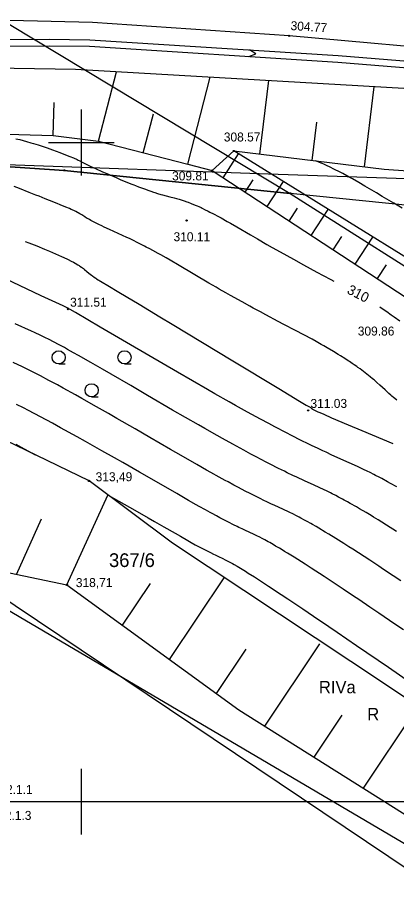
# Model space of a CAD drawing. Extents: x 7477803 to 7478145, y 5500698 to 5500984.
# Drawn here: x 7477945.2 to 7477973.9, y 5500742.3 to 5500809.5 of the extents above; entities that cross this region are included whole.
import ezdxf

# ---------------------------------------------------------------- set-up
doc = ezdxf.new("R2010")
doc.units = 0
for name, color, linetype in [('203-Punkt załamania granicy działki nie stabilizowany', 7, 'Continuous'), ('gr_dzialki', 7, 'Continuous'), ('gr_klasy', 7, 'Continuous'), ('jezdnia', 7, 'Continuous'), ('nr_dzialki', 7, 'Continuous'), ('ogr_symb', 7, 'Continuous'), ('opis_klasy', 7, 'Continuous'), ('opis_uzytek', 7, 'Continuous'), ('pkt_wys', 7, 'Continuous'), ('robocza49', 7, 'Continuous'), ('robocza50', 7, 'Continuous'), ('rowy', 7, 'Continuous'), ('skarp_wypel', 7, 'Continuous'), ('skarpa_dol', 7, 'Continuous'), ('skarpa_gora', 7, 'Continuous'), ('warst_ciagla', 7, 'Continuous'), ('warst_opis', 7, 'Continuous'), ('warst_pogrub', 7, 'Continuous'), ('warst_przeryw', 7, 'Continuous'), ('zakresy', 7, 'Continuous'), ('zielen', 7, 'Continuous')]:
    doc.layers.add(name, color=color, linetype=linetype)

# ---------------------------------------------------------------- blocks, each defined once
blk = doc.blocks.new('203')
blk.add_circle((0, 0), 0.045)
blk = doc.blocks.new('801')
at = {"layer": 'pkt_wys'}
blk.add_circle((0, 0), 0.045, dxfattribs=at)
blk.add_circle((0, 0), 0.045, dxfattribs=at)
blk = doc.blocks.new('941_5')
at = {"layer": 'zielen'}
for p, q in [((-2.5, 0.46), (-2, 0.46)), ((2.5, 0.46), (3, 0.46)), ((0, -2.04), (0.5, -2.04))]:
    blk.add_line(p, q, dxfattribs=at)
for centre in [(-2.503, 0.963), (2.497, 0.963), (-0.003, -1.537)]:
    blk.add_circle(centre, 0.5, dxfattribs=at)
blk = doc.blocks.new('801_5_1')
at = {"layer": 'pkt_wys'}
blk.add_circle((0, 0), 0.05, dxfattribs=at)
blk.add_circle((0, 0), 0.05, dxfattribs=at)
blk = doc.blocks.new('801_5_3')
at = {"layer": 'pkt_wys'}
blk.add_circle((0, 0), 0.05, dxfattribs=at)
blk.add_circle((0, 0), 0.05, dxfattribs=at)

msp = doc.modelspace()

# ---------------------------------------------------------------- linework, layer by layer
at = {"layer": 'gr_dzialki'}
for points in [[(7477942.51, 5500810.15), (7477965.87, 5500796.14)], [(7477933.39, 5500798.91), (7477948.7, 5500797.88)], [(7477948.7, 5500797.88), (7477965.87, 5500796.14)], [(7477965.87, 5500796.14), (7478019.23, 5500762.35)], [(7477980.59, 5500794.64), (7477965.87, 5500796.14)]]:
    msp.add_lwpolyline(points, dxfattribs=at)
at = {"layer": 'gr_klasy'}
for points in [[(7477948.7, 5500797.88), (7477933.39, 5500798.91)], [(7477965.87, 5500796.14), (7477948.7, 5500797.88)], [(7477980.59, 5500794.64), (7477965.87, 5500796.14)]]:
    msp.add_lwpolyline(points, dxfattribs=at)
at = {"layer": 'jezdnia'}
for points in [[(7478007.787, 5500804.444), (7477996.226, 5500805.272), (7477980.454, 5500806.765), (7477965.783, 5500808.078), (7477950.842, 5500809.092), (7477941.412, 5500809.312), (7477933.642, 5500808.883), (7477925.833, 5500807.985), (7477921.044, 5500806.84), (7477908.409, 5500802.106), (7477902.302, 5500799.559), (7477897.005, 5500796.683), (7477891.579, 5500793.077), (7477886.813, 5500789.372), (7477881.349, 5500784.496), (7477881.326, 5500784.471)], [(7477992.069, 5500728.595), (7477992.586, 5500729.366), (7477990.061, 5500731.06), (7477991.702, 5500733.507), (7477933.306, 5500772.671), (7477931.61, 5500770.142), (7477929.08, 5500771.838), (7477927.439, 5500769.391), (7477926.244, 5500770.192), (7477925.336, 5500768.842)]]:
    msp.add_lwpolyline(points, dxfattribs=at)
at = {"layer": 'ogr_symb'}
msp.add_lwpolyline([(7477891.276, 5500779.392), (7477896.666, 5500786.743), (7477921.734, 5500797.99), (7477944.284, 5500798.315), (7477964.224, 5500797.617), (7478003.756, 5500796.28)], dxfattribs=at)
at = {"layer": 'robocza49'}
for p, q in [((7477950, 5500797.5), (7477950, 5500802.5)), ((7477947.5, 5500800), (7477952.5, 5500800)), ((7477950, 5500750), (7477950, 5500752.5)), ((7478000, 5500750), (7477937.375, 5500750)), ((7477950, 5500747.5), (7477950, 5500750))]:
    msp.add_line(p, q, dxfattribs=at)
at = {"layer": 'rowy'}
for points in [[(7477903.253, 5500798.785), (7477908.747, 5500801.483), (7477910.219, 5500802.081), (7477915.822, 5500804.075), (7477918.6, 5500805.006), (7477920.886, 5500805.655), (7477923.298, 5500806.18), (7477925.514, 5500806.496), (7477928.461, 5500806.935), (7477932.972, 5500807.407), (7477936.072, 5500807.618), (7477938.432, 5500807.783), (7477947.546, 5500807.824), (7477950.631, 5500807.793), (7477969.517, 5500806.584), (7477989.191, 5500804.994), (7477997.207, 5500804.282)], [(7477882.663, 5500783.628), (7477883.714, 5500784.691), (7477887.616, 5500787.993), (7477891.069, 5500790.733), (7477893.37, 5500792.367), (7477898.157, 5500795.46), (7477901.645, 5500797.349), (7477903.482, 5500798.34), (7477908.951, 5500801.027), (7477910.397, 5500801.613), (7477915.985, 5500803.602), (7477918.748, 5500804.528), (7477921.007, 5500805.169), (7477923.387, 5500805.687), (7477925.587, 5500806.001), (7477928.524, 5500806.439), (7477933.015, 5500806.909), (7477936.106, 5500807.119), (7477938.45, 5500807.283), (7477947.545, 5500807.324), (7477950.612, 5500807.294), (7477969.481, 5500806.086), (7477989.149, 5500804.495), (7477997.163, 5500803.784)], [(7477962.73, 5500806.518), (7477963.244, 5500806.716), (7477962.762, 5500807.017)]]:
    msp.add_lwpolyline(points, dxfattribs=at)
at = {"layer": 'skarp_wypel'}
for p, q in [((7477951.313, 5500800.09), (7477952.671, 5500805.347)), ((7477958.091, 5500798.34), (7477959.796, 5500804.94)), ((7477963.565, 5500799.118), (7477964.241, 5500804.686)), ((7477971.507, 5500798.154), (7477972.244, 5500804.228)), ((7477947.862, 5500800.525), (7477947.936, 5500803.038)), ((7477954.702, 5500799.215), (7477955.468, 5500802.179)), ((7477967.536, 5500798.636), (7477967.889, 5500801.546)), ((7477960.759, 5500797.321), (7477961.942, 5500799.135)), ((7477962.434, 5500796.228), (7477963.039, 5500797.155)), ((7477964.109, 5500795.135), (7477965.345, 5500797.03)), ((7477965.784, 5500794.042), (7477966.415, 5500795.01)), ((7477967.459, 5500792.95), (7477968.748, 5500794.925)), ((7477969.134, 5500791.857), (7477969.792, 5500792.865)), ((7477970.809, 5500790.764), (7477972.151, 5500792.82)), ((7477972.485, 5500789.671), (7477973.168, 5500790.719)), ((7477948.908, 5500766.44), (7477952.002, 5500773.26)), ((7477945.07, 5500767.244), (7477946.982, 5500771.458)), ((7477953.119, 5500763.388), (7477955.248, 5500766.561)), ((7477956.698, 5500760.795), (7477960.889, 5500767.043)), ((7477963.94, 5500755.734), (7477968.125, 5500761.973)), ((7477960.276, 5500758.201), (7477962.528, 5500761.557)), ((7477967.68, 5500753.381), (7477969.808, 5500756.554)), ((7477971.42, 5500751.028), (7477975.36, 5500756.902))]:
    msp.add_line(p, q, dxfattribs=at)
at = {"layer": 'skarpa_dol'}
msp.add_lwpolyline([(7478003.179, 5500722.859), (7478004.323, 5500725.251), (7478005.298, 5500730.032), (7478003.066, 5500732.439), (7477998.881, 5500736.525), (7477989.029, 5500747.324), (7477982.233, 5500752.776), (7477973.187, 5500758.837), (7477956.935, 5500769.599), (7477950.58, 5500774.332), (7477941.825, 5500778.562), (7477933.581, 5500781.953), (7477926.713, 5500780.256), (7477921.899, 5500775.451), (7477920.234, 5500772.903)], dxfattribs=at)
at = {"layer": 'skarpa_gora'}
for points in [[(7478007.749, 5500802.055), (7477980.618, 5500803.745), (7477949.546, 5500805.521), (7477933.975, 5500805.774), (7477921.168, 5500803.47), (7477908.381, 5500800.266), (7477897.978, 5500794.654), (7477888.325, 5500787.474), (7477883.93, 5500782.828)], [(7477889.282, 5500779.695), (7477895.338, 5500786.582), (7477897.871, 5500788.956), (7477903.767, 5500792.731), (7477909.966, 5500795.925), (7477913.206, 5500797.237), (7477923.556, 5500799.006), (7477930.426, 5500800.345), (7477933.868, 5500800.938), (7477937.366, 5500800.835), (7477947.862, 5500800.525), (7477951.313, 5500800.09), (7477958.091, 5500798.34), (7477959.924, 5500797.862), (7477975.395, 5500787.769), (7477983.174, 5500779.337)], [(7477984.422, 5500781.659), (7477976.623, 5500790.05), (7477961.582, 5500799.354), (7477959.924, 5500797.862)], [(7477961.582, 5500799.354), (7477973.014, 5500797.966), (7477992.005, 5500796.627), (7477997.444, 5500794.449), (7478004.059, 5500795.357)], [(7477924.585, 5500769.172), (7477928.36, 5500773.878), (7477930.919, 5500774.6), (7477933.4, 5500774.083), (7477944.537, 5500767.355), (7477948.908, 5500766.44), (7477961.969, 5500756.974), (7477978.9, 5500746.323), (7477991.003, 5500734.936), (7477993.436, 5500731.709), (7477996, 5500728.251), (7477997.928, 5500724.248)]]:
    msp.add_lwpolyline(points, dxfattribs=at)
at = {"layer": 'warst_ciagla'}
for points in [[(7477974.377, 5500795.015), (7477973.724, 5500795.399), (7477972.855, 5500795.913), (7477972.421, 5500796.172), (7477971.542, 5500796.693), (7477971.081, 5500796.961), (7477970.594, 5500797.236), (7477970.338, 5500797.377), (7477969.86, 5500797.634), (7477969.613, 5500797.763), (7477969.235, 5500797.954), (7477968.853, 5500798.14), (7477968.662, 5500798.231), (7477968.408, 5500798.347), (7477968.282, 5500798.403), (7477968.095, 5500798.484), (7477967.818, 5500798.598)], [(7477945.729, 5500792.496), (7477946.015, 5500792.388), (7477946.21, 5500792.314), (7477946.605, 5500792.158), (7477947.196, 5500791.917), (7477947.576, 5500791.758), (7477947.819, 5500791.654), (7477948.269, 5500791.457), (7477948.495, 5500791.355), (7477948.89, 5500791.17), (7477949.007, 5500791.114), (7477949.219, 5500791.007), (7477949.407, 5500790.908), (7477949.52, 5500790.845), (7477949.721, 5500790.727), (7477949.822, 5500790.663), (7477949.884, 5500790.622), (7477950.001, 5500790.542), (7477950.154, 5500790.429), (7477950.246, 5500790.357), (7477950.41, 5500790.224), (7477950.576, 5500790.09), (7477950.77, 5500789.937), (7477950.856, 5500789.871), (7477950.971, 5500789.786), (7477951.097, 5500789.697), (7477951.149, 5500789.664), (7477951.592, 5500789.409), (7477952.01, 5500789.162), (7477952.857, 5500788.656), (7477953.404, 5500788.328), (7477954.38, 5500787.74), (7477955.971, 5500786.781), (7477956.891, 5500786.226), (7477961.495, 5500783.441), (7477964.992, 5500781.33), (7477965.788, 5500780.851), (7477966.562, 5500780.388), (7477966.826, 5500780.231), (7477967.077, 5500780.083), (7477967.268, 5500779.976), (7477967.317, 5500779.948), (7477967.378, 5500779.911), (7477967.405, 5500779.893), (7477967.444, 5500779.867), (7477967.49, 5500779.833), (7477967.51, 5500779.816), (7477967.54, 5500779.792), (7477967.562, 5500779.777), (7477967.613, 5500779.747), (7477967.755, 5500779.676), (7477967.972, 5500779.575), (7477968.123, 5500779.508), (7477968.409, 5500779.382), (7477968.998, 5500779.126), (7477970.264, 5500778.587), (7477971.305, 5500778.148), (7477973.668, 5500777.157)], [(7477973.951, 5500770.497), (7477973.191, 5500770.978), (7477972.822, 5500771.207), (7477972.551, 5500771.374), (7477972.196, 5500771.59), (7477972.022, 5500771.695), (7477971.637, 5500771.925), (7477971.14, 5500772.217), (7477970.898, 5500772.356), (7477970.427, 5500772.623), (7477970.223, 5500772.735), (7477969.958, 5500772.881), (7477969.827, 5500772.951), (7477969.539, 5500773.105), (7477969.328, 5500773.215), (7477969.054, 5500773.355), (7477968.92, 5500773.422), (7477968.625, 5500773.566), (7477968.433, 5500773.659), (7477968.057, 5500773.835), (7477967.687, 5500774.004), (7477966.943, 5500774.34), (7477966.363, 5500774.606), (7477966.059, 5500774.749), (7477965.638, 5500774.951), (7477965.422, 5500775.057), (7477964.975, 5500775.279), (7477964.352, 5500775.594), (7477964.029, 5500775.76), (7477963.273, 5500776.156), (7477962.88, 5500776.365), (7477962.341, 5500776.654), (7477962.065, 5500776.804), (7477961.5, 5500777.113), (7477960.718, 5500777.546), (7477960.316, 5500777.771), (7477959.382, 5500778.298), (7477958.901, 5500778.572), (7477957.92, 5500779.135), (7477956.933, 5500779.706), (7477955.032, 5500780.81), (7477953.747, 5500781.556), (7477952.251, 5500782.423), (7477951.595, 5500782.802), (7477950.729, 5500783.301), (7477949.79, 5500783.838), (7477949.413, 5500784.052), (7477948.957, 5500784.309), (7477948.706, 5500784.448), (7477948.266, 5500784.684), (7477947.941, 5500784.853), (7477947.496, 5500785.078), (7477947.268, 5500785.19), (7477946.92, 5500785.358), (7477946.444, 5500785.582), (7477946.2, 5500785.693), (7477944.962, 5500786.248)], [(7477974.461, 5500763.023), (7477973.819, 5500763.463), (7477972.587, 5500764.303), (7477971.925, 5500764.752), (7477971.078, 5500765.324), (7477970.67, 5500765.598), (7477969.885, 5500766.123), (7477968.901, 5500766.774), (7477968.437, 5500767.079), (7477967.458, 5500767.716), (7477967.003, 5500768.007), (7477966.433, 5500768.37), (7477966.163, 5500768.539), (7477965.654, 5500768.854), (7477965.441, 5500768.985), (7477965.169, 5500769.149), (7477965.039, 5500769.227), (7477964.759, 5500769.392), (7477964.561, 5500769.507), (7477964.312, 5500769.649), (7477964.195, 5500769.714), (7477963.947, 5500769.85), (7477963.793, 5500769.931), (7477963.507, 5500770.077), (7477963.374, 5500770.143), (7477963.121, 5500770.265), (7477962.405, 5500770.595), (7477962.219, 5500770.683), (7477961.962, 5500770.806), (7477961.83, 5500770.871), (7477961.557, 5500771.006), (7477961.176, 5500771.199), (7477960.979, 5500771.3), (7477960.517, 5500771.542), (7477960.277, 5500771.67), (7477959.948, 5500771.846), (7477959.779, 5500771.938), (7477959.434, 5500772.127), (7477958.957, 5500772.391), (7477958.711, 5500772.528), (7477958.14, 5500772.85), (7477957.242, 5500773.364), (7477955.358, 5500774.453), (7477954.406, 5500775.001), (7477953.14, 5500775.724), (7477952.508, 5500776.083), (7477951.561, 5500776.616), (7477950.302, 5500777.321), (7477949.674, 5500777.671), (7477948.422, 5500778.361), (7477947.802, 5500778.699), (7477946.885, 5500779.193), (7477945.988, 5500779.667), (7477945.597, 5500779.871), (7477945.081, 5500780.137)]]:
    msp.add_lwpolyline(points, dxfattribs=at)
at = {"layer": 'warst_pogrub'}
for points in [[(7477945.034, 5500800.285), (7477945.317, 5500800.212), (7477945.825, 5500800.076), (7477946.158, 5500799.983), (7477946.36, 5500799.925), (7477946.719, 5500799.817), (7477946.878, 5500799.767), (7477947.162, 5500799.674), (7477947.407, 5500799.589), (7477947.813, 5500799.44), (7477948.362, 5500799.233), (7477948.659, 5500799.12), (7477949.126, 5500798.937), (7477949.399, 5500798.827), (7477949.671, 5500798.711), (7477949.768, 5500798.666), (7477949.871, 5500798.612), (7477949.986, 5500798.546), (7477950.06, 5500798.505), (7477950.22, 5500798.424), (7477950.528, 5500798.277), (7477950.722, 5500798.186), (7477951.065, 5500798.03), (7477951.617, 5500797.783), (7477951.934, 5500797.643), (7477952.638, 5500797.336), (7477953.01, 5500797.176), (7477953.568, 5500796.943), (7477953.75, 5500796.869), (7477953.989, 5500796.773), (7477954.107, 5500796.727), (7477954.339, 5500796.637), (7477954.641, 5500796.524), (7477954.789, 5500796.47), (7477955.113, 5500796.355), (7477955.272, 5500796.301), (7477955.479, 5500796.233), (7477955.58, 5500796.2), (7477955.78, 5500796.137), (7477956.039, 5500796.06), (7477956.166, 5500796.023), (7477956.443, 5500795.949), (7477956.71, 5500795.882), (7477957.061, 5500795.796), (7477957.239, 5500795.75), (7477957.421, 5500795.7), (7477957.515, 5500795.672), (7477957.658, 5500795.628), (7477957.807, 5500795.579), (7477958.012, 5500795.506), (7477958.118, 5500795.467), (7477958.337, 5500795.381), (7477958.643, 5500795.254), (7477958.801, 5500795.185), (7477958.923, 5500795.13), (7477959.088, 5500795.054), (7477959.172, 5500795.015), (7477959.365, 5500794.923), (7477959.63, 5500794.793), (7477959.766, 5500794.724), (7477960.044, 5500794.581), (7477960.429, 5500794.378), (7477960.627, 5500794.27), (7477961.087, 5500794.014), (7477961.325, 5500793.879), (7477961.814, 5500793.597), (7477962.839, 5500792.996), (7477963.37, 5500792.685), (7477964.101, 5500792.263), (7477964.484, 5500792.045), (7477965.094, 5500791.702), (7477966.115, 5500791.137), (7477966.876, 5500790.722), (7477967.895, 5500790.171), (7477968.363, 5500789.921), (7477968.958, 5500789.607), (7477969.189, 5500789.487)], [(7477972.684, 5500787.521), (7477972.86, 5500787.405), (7477973.204, 5500787.171), (7477973.54, 5500786.938), (7477973.759, 5500786.782), (7477974.185, 5500786.471)]]:
    msp.add_lwpolyline(points, dxfattribs=at)
at = {"layer": 'warst_przeryw'}
for points in [[(7477973.954, 5500780.457), (7477973.818, 5500780.568), (7477973.717, 5500780.653), (7477973.583, 5500780.768), (7477973.516, 5500780.826), (7477973.367, 5500780.958), (7477973.07, 5500781.229), (7477972.665, 5500781.602), (7477972.453, 5500781.793), (7477972.232, 5500781.986), (7477972.117, 5500782.084), (7477971.939, 5500782.231), (7477971.691, 5500782.429), (7477971.562, 5500782.529), (7477971.295, 5500782.73), (7477971.172, 5500782.82), (7477971.005, 5500782.94), (7477970.919, 5500783.001), (7477970.723, 5500783.138), (7477970.572, 5500783.241), (7477970.366, 5500783.379), (7477970.261, 5500783.449), (7477970.019, 5500783.606), (7477969.685, 5500783.817), (7477969.514, 5500783.923), (7477969.162, 5500784.138), (7477968.672, 5500784.426), (7477968.419, 5500784.572), (7477968.226, 5500784.682), (7477967.963, 5500784.829), (7477967.829, 5500784.903), (7477967.524, 5500785.07), (7477966.896, 5500785.407), (7477966.254, 5500785.745), (7477965.39, 5500786.197), (7477964.961, 5500786.422), (7477964.014, 5500786.924), (7477963.602, 5500787.145), (7477963.061, 5500787.437), (7477962.794, 5500787.582), (7477962.203, 5500787.907), (7477961.339, 5500788.39), (7477960.964, 5500788.602), (7477960.472, 5500788.883), (7477960.23, 5500789.022), (7477959.693, 5500789.334), (7477957.432, 5500790.674), (7477956.733, 5500791.078), (7477956.431, 5500791.249), (7477956.036, 5500791.469), (7477955.843, 5500791.576), (7477955.416, 5500791.807), (7477955.207, 5500791.919), (7477954.934, 5500792.063), (7477954.799, 5500792.133), (7477954.533, 5500792.27), (7477954.188, 5500792.443), (7477954.019, 5500792.527), (7477953.647, 5500792.706), (7477953.465, 5500792.792), (7477953.112, 5500792.955), (7477952.147, 5500793.39), (7477951.725, 5500793.584), (7477951.552, 5500793.666), (7477951.334, 5500793.771), (7477951.231, 5500793.822), (7477951.012, 5500793.931), (7477950.721, 5500794.085), (7477950.605, 5500794.149), (7477950.464, 5500794.229), (7477950.399, 5500794.268), (7477950.267, 5500794.351), (7477950.031, 5500794.508), (7477949.886, 5500794.595), (7477949.764, 5500794.662), (7477949.694, 5500794.699), (7477949.573, 5500794.76), (7477949.432, 5500794.827), (7477949.213, 5500794.926), (7477949.09, 5500794.981), (7477948.817, 5500795.099), (7477948.397, 5500795.275), (7477948.163, 5500795.371), (7477947.578, 5500795.607), (7477947.255, 5500795.735), (7477946.793, 5500795.917), (7477946.549, 5500796.012), (7477946.033, 5500796.211), (7477945.289, 5500796.496), (7477944.893, 5500796.647)], [(7477973.954, 5500773.884), (7477973.493, 5500774.14), (7477973.265, 5500774.265), (7477972.813, 5500774.507), (7477972.615, 5500774.611), (7477972.352, 5500774.747), (7477972.221, 5500774.814), (7477971.929, 5500774.961), (7477971.712, 5500775.068), (7477971.425, 5500775.207), (7477971.282, 5500775.276), (7477970.964, 5500775.425), (7477970.332, 5500775.713), (7477969.037, 5500776.292), (7477968.583, 5500776.499), (7477968.349, 5500776.607), (7477967.989, 5500776.777), (7477967.491, 5500777.015), (7477967.235, 5500777.14), (7477966.708, 5500777.401), (7477965.973, 5500777.772), (7477965.592, 5500777.968), (7477964.703, 5500778.432), (7477964.242, 5500778.677), (7477963.609, 5500779.017), (7477963.285, 5500779.192), (7477962.622, 5500779.554), (7477961.708, 5500780.06), (7477961.237, 5500780.323), (7477960.145, 5500780.939), (7477959.583, 5500781.259), (7477958.44, 5500781.915), (7477957.296, 5500782.576), (7477955.124, 5500783.839), (7477951.44, 5500785.987), (7477949.542, 5500787.094), (7477949.138, 5500787.331), (7477949.059, 5500787.38), (7477949.013, 5500787.41), (7477948.992, 5500787.425), (7477948.966, 5500787.439), (7477948.926, 5500787.455), (7477948.814, 5500787.505), (7477948.608, 5500787.6), (7477946.947, 5500788.378), (7477943.677, 5500789.913)], [(7477974.263, 5500766.751), (7477973.694, 5500767.134), (7477972.962, 5500767.622), (7477972.606, 5500767.857), (7477971.918, 5500768.31), (7477971.046, 5500768.876), (7477970.629, 5500769.143), (7477970.326, 5500769.337), (7477969.932, 5500769.585), (7477969.74, 5500769.705), (7477969.32, 5500769.966), (7477968.786, 5500770.293), (7477968.53, 5500770.448), (7477968.04, 5500770.738), (7477967.832, 5500770.86), (7477967.564, 5500771.015), (7477967.433, 5500771.089), (7477967.149, 5500771.248), (7477966.944, 5500771.361), (7477966.683, 5500771.502), (7477966.557, 5500771.568), (7477966.286, 5500771.708), (7477966.113, 5500771.795), (7477965.782, 5500771.956), (7477965.311, 5500772.176), (7477964.698, 5500772.456), (7477964.384, 5500772.601), (7477964.139, 5500772.716), (7477963.8, 5500772.879), (7477963.626, 5500772.964), (7477963.266, 5500773.142), (7477962.764, 5500773.396), (7477962.504, 5500773.53), (7477961.895, 5500773.849), (7477961.579, 5500774.017), (7477961.145, 5500774.25), (7477960.922, 5500774.371), (7477960.467, 5500774.62), (7477959.837, 5500774.968), (7477959.513, 5500775.15), (7477958.761, 5500775.574), (7477957.581, 5500776.25), (7477956.778, 5500776.714), (7477955.195, 5500777.632), (7477954.077, 5500778.279), (7477952.695, 5500779.074), (7477952.052, 5500779.442), (7477951.145, 5500779.959), (7477950.046, 5500780.58), (7477949.544, 5500780.861), (7477948.621, 5500781.372), (7477948.186, 5500781.609), (7477947.541, 5500781.953), (7477946.886, 5500782.295), (7477946.589, 5500782.446), (7477946.189, 5500782.648), (7477945.986, 5500782.749), (7477945.526, 5500782.976), (7477944.823, 5500783.315)], [(7477945.027, 5500777.12), (7477945.425, 5500776.898), (7477946.48, 5500776.313)], [(7477952.047, 5500773.239), (7477953.241, 5500772.571), (7477954.055, 5500772.112), (7477955.077, 5500771.531), (7477955.56, 5500771.254), (7477956.252, 5500770.855), (7477957.114, 5500770.358), (7477957.519, 5500770.127), (7477958.097, 5500769.802), (7477958.341, 5500769.667), (7477958.656, 5500769.494), (7477958.808, 5500769.412), (7477959.139, 5500769.235), (7477959.605, 5500768.993), (7477959.8, 5500768.894), (7477960.049, 5500768.77), (7477960.169, 5500768.712), (7477960.426, 5500768.59), (7477960.755, 5500768.437), (7477960.93, 5500768.353), (7477961.125, 5500768.255), (7477961.232, 5500768.199), (7477961.473, 5500768.068), (7477961.608, 5500767.991), (7477961.832, 5500767.861), (7477962.086, 5500767.709), (7477962.47, 5500767.474), (7477962.681, 5500767.342), (7477963.144, 5500767.049), (7477963.842, 5500766.6), (7477964.227, 5500766.35), (7477965.176, 5500765.726), (7477965.695, 5500765.381), (7477966.433, 5500764.889), (7477966.822, 5500764.628), (7477967.639, 5500764.079), (7477968.81, 5500763.286), (7477969.43, 5500762.865), (7477970.911, 5500761.855), (7477973.325, 5500760.199), (7477974.996, 5500759.047)]]:
    msp.add_lwpolyline(points, dxfattribs=at)
at = {"layer": 'zakresy'}
msp.add_lwpolyline([(7477995.059, 5500962.348), (7477983.951, 5500968.084), (7477970.781, 5500968.613), (7477936.09, 5500958.171), (7477930.511, 5500954.336), (7477914.305, 5500958.58), (7477904.32, 5500957.41), (7477897.265, 5500950.868), (7477811.424, 5500829.338), (7477936.003, 5500769.492), (7478008.982, 5500726.585), (7478019.402, 5500721.781), (7478037.95, 5500734.97), (7478039.493, 5500755.094), (7478043.98, 5500765.708), (7478067.545, 5500795.068), (7478092.109, 5500820.25), (7478076.156, 5500837.989), (7478068.105, 5500851.146), (7478061.422, 5500873.298), (7478054.135, 5500876.371), (7478039.669, 5500897.644), (7478026.36, 5500915.23), (7478015.054, 5500927.728)], close=True, dxfattribs=at)

# ---------------------------------------------------------------- block references
at = {"layer": '203-Punkt załamania granicy działki nie stabilizowany'}
for p in [(7477948.7, 5500797.88), (7477965.87, 5500796.14)]:
    msp.add_blockref('203', p, dxfattribs=at)
at = {"layer": 'pkt_wys', "rotation": 0.0626175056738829}
for name, p in [('801_5_1', (7477965.783, 5500808.078)), ('801', (7477961.582, 5500799.354)), ('801', (7477959.924, 5500797.862)), ('801', (7477957.998, 5500794.08)), ('801', (7477948.976, 5500787.36)), ('801', (7477967.234, 5500779.68)), ('801_5_3', (7477950.58, 5500774.332)), ('801_5_3', (7477948.908, 5500766.44))]:
    msp.add_blockref(name, p, dxfattribs=at)
at = {"layer": 'zielen', "rotation": 0.0626175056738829}
msp.add_blockref('941_5', (7477950.78, 5500782.741), dxfattribs=at)

# ---------------------------------------------------------------- texts
at = {"layer": 'nr_dzialki'}
msp.add_text('367/6', height=1.04, dxfattribs=at).set_placement((7477952.102, 5500767.799))
at = {"layer": 'opis_klasy'}
msp.add_text('RIVa', height=0.94, dxfattribs=at).set_placement((7477968.045, 5500758.222))
at = {"layer": 'opis_uzytek'}
msp.add_text('R', height=0.94, dxfattribs=at).set_placement((7477971.717, 5500756.17))
at = {"layer": 'pkt_wys'}
for s, rotation, p in [('304.77', 356.51576, (7477965.876, 5500808.526)), ('308.57', 0.06262, (7477960.82, 5500800.072)), ('309.81', 0.06262, (7477956.892, 5500797.12)), ('310.11', 0.06262, (7477956.999, 5500792.508)), ('311.51', 0.06262, (7477949.144, 5500787.544)), ('309.86', 0.06262, (7477970.997, 5500785.353)), ('311.03', 0.06262, (7477967.403, 5500779.864)), ('313,49', 0.06262, (7477951.084, 5500774.304)), ('318,71', 0.06262, (7477949.58, 5500766.276))]:
    msp.add_text(s, height=0.68, rotation=rotation, dxfattribs=at).set_placement(p)
at = {"layer": 'robocza50'}
for s, p in [('7.116.18.22.1.1', (7477939.978, 5500750.59)), ('7.116.18.22.1.3', (7477939.886, 5500748.62))]:
    msp.add_text(s, height=0.68, dxfattribs=at).set_placement(p)
at = {"layer": 'warst_opis'}
msp.add_text('310', height=0.75, rotation=332.81503, dxfattribs=at).set_placement((7477970.119, 5500788.588))

doc.saveas('drawing.dxf')
